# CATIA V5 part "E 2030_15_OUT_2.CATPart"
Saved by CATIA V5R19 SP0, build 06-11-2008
Material "Plastic": density 1200 kg/m3, Young's modulus 2.2e+09 Pa, Poisson ratio 0.38, thermal expansion 6.84e-05 1/K
Bounding box of the stored display mesh (mm): x 15.1 to 30.2, y -7.54 to 7.54, z -2 to 0
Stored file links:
  G:\UTB\Kombinované\Bakalářská práce\Catia\FORMA\E 2030_15_OUT_2.CATPart
  D:\Aplikace\CATIA\Nová složka\win_b64\startup\materials\Catalog.CATMaterial
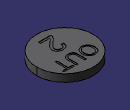
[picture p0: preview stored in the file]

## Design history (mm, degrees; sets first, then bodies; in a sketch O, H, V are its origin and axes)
Body1 "E 2030_15_OUT_1-8" (main body)
  Solid1: solid without history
